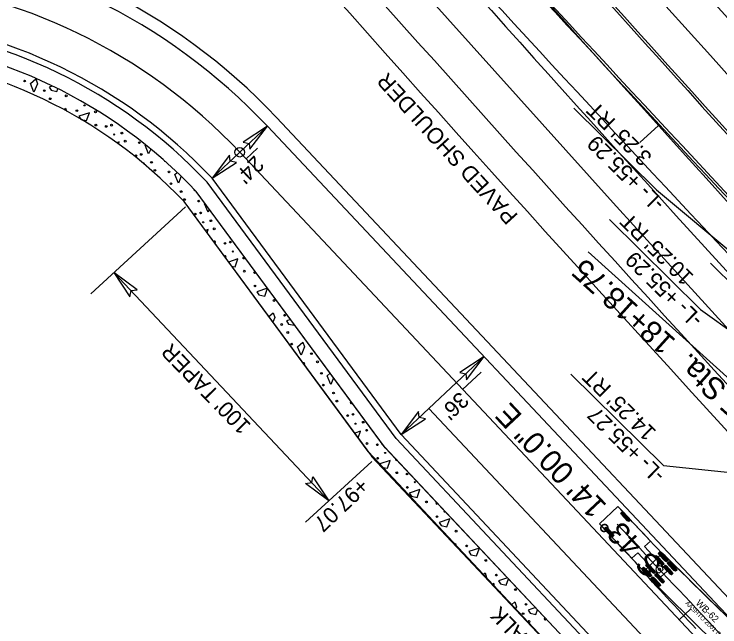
# Model space of a CAD drawing. Extents: x 1262642 to 1268358, y 767825 to 773481.
# Drawn here: x 1266385.4 to 1266608.5, y 772219.4 to 772413.2 of the extents above; entities that cross this region are included whole.
import ezdxf

# ---------------------------------------------------------------- set-up
doc = ezdxf.new("R2010")
doc.units = 0
for name, color, linetype in [('Default', 7, 'Continuous'), ('Prop Conc 1ft 6in Curb and Gutter', 7, 'Continuous'), ('Prop Conc 2ft 6in Curb and Gutter', 7, 'Continuous'), ('Prop Conc 4in Sidewalk', 7, 'Continuous'), ('Prop Dimension', 7, 'Continuous'), ('Prop Dimension Text', 7, 'Continuous'), ('Prop EOT', 7, 'Continuous'), ('Prop Horizontal Alignment', 7, 'Continuous'), ('Prop Horizontal Alignment Direction Label', 7, 'Continuous'), ('Prop Horizontal Alignment Station Label', 7, 'Continuous'), ('Prop Horizontal Alignment Tick Large', 7, 'Continuous'), ('Prop Horizontal Alignment Tick Small', 7, 'Continuous'), ('Prop Lane Lines', 7, 'Continuous'), ('Prop Paved Shoulder', 7, 'Continuous'), ('Prop Shade Light', 7, 'Continuous'), ('Prop Terminator CELL', 7, 'Continuous'), ('Scratch_Level_3', 7, 'Continuous')]:
    doc.layers.add(name, color=color, linetype=linetype)

msp = doc.modelspace()

# ---------------------------------------------------------------- linework, layer by layer
at = {"layer": 'Default'}
for p, q in [((1266447.96, 772361.32), (1266465.44, 772377.76)), ((1266507.71, 772280.24), (1266533.94, 772304.9))]:
    msp.add_line(p, q, dxfattribs=at)
at = {"layer": 'Prop Conc 1ft 6in Curb and Gutter'}
for centre, radius, start, end in [((1275047.31, 780021.23), 11385.75, 220.946412, 223.103661), ((1274932.68, 780143.08), 11396.75, 221.786199, 223.669794)]:
    msp.add_arc(centre, radius, start, end, dxfattribs=at)
at = {"layer": 'Prop Conc 2ft 6in Curb and Gutter'}
for p, q in [((1266390.56, 772391.24), (1266392.25, 772392.74)), ((1266391.64, 772388.56), (1266390.56, 772391.24)), ((1266392.77, 772391.21), (1266391.64, 772388.56)), ((1266392.25, 772392.74), (1266392.77, 772391.21)), ((1266397.45, 772390.49), (1266396.47, 772390.16)), ((1266396.47, 772390.16), (1266397.11, 772389.17)), ((1266397.11, 772389.17), (1266398.92, 772388.8)), ((1266398.92, 772388.8), (1266399.22, 772389.61)), ((1266401.08, 772383.01), (1266401.63, 772383.49)), ((1266401.63, 772383.49), (1266401.95, 772382.56)), ((1266409.22, 772382.05), (1266405.85, 772380.91)), ((1266405.85, 772380.91), (1266406.49, 772379.94)), ((1266406.53, 772379.92), (1266408.3, 772379.55)), ((1266408.3, 772379.55), (1266409.22, 772382.05)), ((1266418.61, 772372.8), (1266417.8, 772372.53)), ((1266418.36, 772372.13), (1266418.61, 772372.8)), ((1266426.83, 772371.75), (1266426.96, 772371.86)), ((1266427.91, 772369.07), (1266426.83, 772371.75)), ((1266428.55, 772370.56), (1266427.91, 772369.07)), ((1266436.22, 772362.5), (1266436.94, 772363.14)), ((1266437.3, 772359.82), (1266436.22, 772362.5)), ((1266438.21, 772361.96), (1266437.3, 772359.82)), ((1266506.17, 772278.96), (1266446.42, 772360.04)), ((1266502.71, 772276.07), (1266442.96, 772357.15)), ((1266497.36, 772274.9), (1266439.11, 772353.93)), ((1266445.6, 772353.26), (1266445.74, 772353.38)), ((1266446.68, 772350.58), (1266445.6, 772353.26)), ((1266447.09, 772351.54), (1266446.68, 772350.58)), ((1266446.76, 772345.07), (1266445.87, 772344.77)), ((1266446.39, 772344.06), (1266446.76, 772345.07)), ((1266456.14, 772335.82), (1266453.2, 772334.83)), ((1266455.22, 772333.32), (1266456.14, 772335.82)), ((1266454.14, 772333.55), (1266455.22, 772333.32)), ((1266465.5, 772326.57), (1266462.16, 772325.44)), ((1266464.61, 772324.08), (1266465.51, 772326.54)), ((1266462.16, 772325.44), (1266462.8, 772324.45)), ((1266462.8, 772324.45), (1266464.61, 772324.08)), ((1266465.93, 772317.55), (1266467.31, 772318.77)), ((1266467.31, 772318.77), (1266467.84, 772317.24)), ((1266467.84, 772317.24), (1266467.22, 772315.8)), ((1266472.82, 772316.62), (1266471.54, 772316.19)), ((1266471.54, 772316.19), (1266472.18, 772315.21)), ((1266472.18, 772315.21), (1266473.99, 772314.83)), ((1266473.99, 772314.83), (1266474.04, 772314.97)), ((1266475.01, 772308.03), (1266476.7, 772309.53)), ((1266476.7, 772309.53), (1266477.22, 772307.99)), ((1266476.09, 772305.35), (1266475.01, 772308.03)), ((1266477.22, 772307.99), (1266476.09, 772305.35)), ((1266484.4, 772298.79), (1266485.35, 772299.63)), ((1266485.48, 772296.11), (1266484.4, 772298.79)), ((1266486.38, 772298.23), (1266485.48, 772296.11)), ((1266494.93, 772281.35), (1266493.07, 772280.72)), ((1266494.16, 772279.24), (1266494.93, 772281.35)), ((1266506.17, 772278.96), (1266647.88, 772128.24)), ((1266502.71, 772276.07), (1266644.44, 772125.33)), ((1266497.36, 772274.9), (1266640.83, 772121.86)), ((1266504.32, 772272.1), (1266501.03, 772270.99)), ((1266503.4, 772269.6), (1266504.32, 772272.1)), ((1266502.07, 772269.88), (1266503.4, 772269.6)), ((1266513.7, 772262.86), (1266510.33, 772261.72)), ((1266510.33, 772261.72), (1266510.98, 772260.73)), ((1266512.78, 772260.36), (1266513.7, 772262.86)), ((1266510.98, 772260.73), (1266512.78, 772260.36)), ((1266523.09, 772253.61), (1266519.72, 772252.47)), ((1266522.17, 772251.11), (1266523.09, 772253.61)), ((1266519.72, 772252.47), (1266520.36, 772251.49)), ((1266520.36, 772251.49), (1266522.17, 772251.11)), ((1266524.74, 772245.69), (1266524.88, 772245.81)), ((1266524.88, 772245.81), (1266525.01, 772245.4)), ((1266532.47, 772244.36), (1266529.1, 772243.23)), ((1266531.55, 772241.87), (1266532.47, 772244.36)), ((1266529.1, 772243.23), (1266529.74, 772242.24)), ((1266529.74, 772242.24), (1266531.55, 772241.87)), ((1266533.74, 772236.1), (1266534.26, 772236.56)), ((1266534.26, 772236.56), (1266534.78, 772235.03)), ((1266534.78, 772235.03), (1266534.77, 772235)), ((1266541.37, 772234.96), (1266538.48, 772233.98)), ((1266538.48, 772233.98), (1266539.13, 772233)), ((1266539.13, 772233), (1266540.93, 772232.62)), ((1266540.93, 772232.62), (1266541.67, 772234.63)), ((1266542.73, 772226.51), (1266543.64, 772227.32)), ((1266543.64, 772227.32), (1266544.17, 772225.78)), ((1266544.17, 772225.78), (1266543.93, 772225.23)), ((1266550.23, 772225.53), (1266547.87, 772224.73)), ((1266547.87, 772224.73), (1266548.51, 772223.75)), ((1266548.51, 772223.75), (1266550.32, 772223.37)), ((1266550.32, 772223.37), (1266550.86, 772224.86))]:
    msp.add_line(p, q, dxfattribs=at)
for centre, radius in [((1266388.7, 772392.07), 0.268), ((1266394.91, 772389.04), 0.268), ((1266396.81, 772386.49), 0.292), ((1266401.86, 772387.39), 0.289), ((1266407.61, 772384.38), 0.18), ((1266405.22, 772382.72), 0.268), ((1266411.12, 772382.32), 0.285), ((1266411.24, 772378.14), 0.289), ((1266414.51, 772377.72), 0.268), ((1266416.19, 772378.11), 0.268), ((1266419.43, 772375.61), 0.268), ((1266416.99, 772375.14), 0.18), ((1266420.51, 772373.07), 0.285), ((1266424.97, 772372.58), 0.268), ((1266423.9, 772368.47), 0.268), ((1266425.57, 772368.86), 0.268), ((1266428.81, 772366.37), 0.268), ((1266429.89, 772363.83), 0.285), ((1266434.36, 772363.33), 0.268), ((1266434.96, 772359.61), 0.268), ((1266438.19, 772357.12), 0.268), ((1266439.27, 772354.58), 0.285), ((1266443.74, 772354.09), 0.268), ((1266442.66, 772349.98), 0.268), ((1266444.34, 772350.37), 0.268), ((1266445.14, 772347.4), 0.18), ((1266447.58, 772347.87), 0.268), ((1266448.66, 772345.34), 0.285), ((1266452.05, 772340.73), 0.268), ((1266453.72, 772341.12), 0.268), ((1266454.53, 772338.16), 0.18), ((1266458.04, 772336.09), 0.285), ((1266458.16, 772331.91), 0.289), ((1266461.43, 772331.49), 0.268), ((1266461.52, 772327.25), 0.268), ((1266467.54, 772322.67), 0.289), ((1266470.9, 772318), 0.268), ((1266469.98, 772315.07), 0.268), ((1266471.88, 772312.52), 0.292), ((1266473.15, 772308.86), 0.268), ((1266479.37, 772305.82), 0.268), ((1266481.27, 772303.28), 0.292), ((1266482.53, 772299.62), 0.268), ((1266483.13, 772295.9), 0.268), ((1266486.37, 772293.4), 0.268), ((1266487.45, 772290.86), 0.285), ((1266490.84, 772286.26), 0.268), ((1266492.52, 772286.65), 0.268), ((1266495.76, 772284.16), 0.268), ((1266493.32, 772283.68), 0.18), ((1266496.84, 772281.62), 0.285), ((1266496.95, 772277.44), 0.289), ((1266500.22, 772277.02), 0.268), ((1266500.31, 772272.78), 0.268), ((1266502.7, 772274.44), 0.18), ((1266506.34, 772268.19), 0.289), ((1266509.61, 772267.77), 0.268), ((1266512.09, 772265.19), 0.18), ((1266509.7, 772263.53), 0.268), ((1266515.72, 772258.95), 0.289), ((1266519.08, 772254.29), 0.268), ((1266525.11, 772249.7), 0.289), ((1266528.46, 772245.04), 0.268), ((1266534.49, 772240.46), 0.289), ((1266537.85, 772235.79), 0.268), ((1266543.87, 772231.21), 0.289), ((1266547.23, 772226.55), 0.268), ((1266546.31, 772223.61), 0.268)]:
    msp.add_circle(centre, radius, dxfattribs=at)
for centre, radius, start, end in [((1266329.2, 772249.67), 161, 43.2758, 125.8167), ((1266329.2, 772249.67), 156.5, 43.3742, 125.8167), ((1266329.2, 772249.67), 151.5, 43.4886, 125.8167), ((1266433.09, 772366.99), 0.292, 186.536, 271.698), ((1266426.38, 772365.89), 0.18, 350.1757, 149.8364), ((1266426.38, 772365.89), 0.18, 309.7917, 350.1757), ((1266442.47, 772357.75), 0.292, 150.1108, 299.1636), ((1266448.78, 772341.16), 0.289, 263.1236, 169.6575), ((1266452.14, 772336.5), 0.268, 275.6877, 157.0934), ((1266463.91, 772328.91), 0.18, 165.6129, 267.1682), ((1266462.5, 772321.77), 0.292, 8.8332, 63.9479), ((1266476.99, 772302.65), 0.268, 293.3734, 139.4078), ((1266483.94, 772292.93), 0.18, 344.51, 88.2711), ((1266491.92, 772290.37), 0.268, 76.2831, 356.498), ((1266501.9, 772277.4), 0.268, 157.7095, 275.0716), ((1266506.22, 772272.37), 0.285, 137.8046, 308.6621), ((1266518.99, 772258.52), 0.268, 97.1815, 349.2851), ((1266521.47, 772255.95), 0.18, 92.5925, 353.8742), ((1266536.93, 772232.86), 0.268, 288.311, 157.9917), ((1266538.83, 772230.31), 0.292, 9.7383, 76.5643), ((1266553.26, 772221.96), 0.289, 78.3196, 8.1471), ((1266548.21, 772221.07), 0.292, 240.1864, 206.1162)]:
    msp.add_arc(centre, radius, start, end, dxfattribs=at)
at = {"layer": 'Prop Conc 4in Sidewalk'}
for p, q in [((1266502.48, 772276.39), (1266442.96, 772357.15)), ((1266498.45, 772273.42), (1266439.11, 772353.93)), ((1266502.44, 772276.36), (1266644.6, 772125.15)), ((1266498.39, 772273.36), (1266640.96, 772121.73))]:
    msp.add_line(p, q, dxfattribs=at)
for radius, start in [(156.5, 43.3742), (151.5, 43.4886)]:
    msp.add_arc((1266329.2, 772249.67), radius, start, 125.8167, dxfattribs=at)
at = {"layer": 'Prop Dimension Text'}
for p, q in [((1266562.29, 772383.47), (1266588.48, 772357.65)), ((1266588.48, 772357.65), (1266689.12, 772273.54)), ((1266439.59, 772352.32), (1266409.59, 772324.77)), ((1266573.6, 772348.23), (1266602.44, 772319.81)), ((1266605.51, 772334.48), (1266637.67, 772302.8)), ((1266484.88, 772259.28), (1266416.95, 772331.53)), ((1266602.44, 772319.81), (1266679.28, 772264.3)), ((1266561.38, 772299.36), (1266590.66, 772270.5)), ((1266498.46, 772271.75), (1266477.52, 772252.52)), ((1266590.66, 772270.5), (1266676.36, 772261.56))]:
    msp.add_line(p, q, dxfattribs=at)
for points in [[(1266424.25, 772326.04), (1266416.95, 772331.53), (1266421.99, 772323.84), (1266422.37, 772325.78)], [(1266479.85, 772266.9), (1266484.88, 772259.28), (1266477.52, 772264.78), (1266479.47, 772265.04)]]:
    msp.add_lwpolyline(points, close=True, dxfattribs=at)
at = {"layer": 'Prop EOT'}
for p, q in [((1266465.44, 772377.76), (1266608.52, 772225.58)), ((1266507.71, 772280.24), (1266447.96, 772361.32)), ((1266507.71, 772280.24), (1266649.33, 772129.6))]:
    msp.add_line(p, q, dxfattribs=at)
for centre, radius, start, end in [((1275047.31, 780021.23), 11361, 216.766365, 222.716029), ((1275047.31, 780021.23), 11439, 220.505091, 222.993587), ((1275047.31, 780021.23), 11385, 220.946412, 222.993587), ((1274932.68, 780143.08), 11397.5, 221.785983, 223.669794), ((1266329.2, 772249.67), 187, 43.2333, 84.9916), ((1266329.2, 772249.67), 163, 43.2333, 125.8167), ((1266840.27, 772443.46), 318.09, 223.2333, 243.6532)]:
    msp.add_arc(centre, radius, start, end, dxfattribs=at)
at = {"layer": 'Prop Horizontal Alignment'}
msp.add_line((1266456.7, 772369.54), (1266660.64, 772152.62), dxfattribs=at)
for centre, radius, start, end in [((1275047.31, 780021.23), 11400, 216.766365, 222.993587), ((1266329.2, 772249.67), 175, 43.2333, 125.8167)]:
    msp.add_arc(centre, radius, start, end, dxfattribs=at)
at = {"layer": 'Prop Horizontal Alignment Station Label'}
msp.add_line((1266769.82, 772154.72), (1266566.88, 772338.06), dxfattribs=at)
msp.add_circle((1266456.7, 772369.54), 1.5, dxfattribs=at)
at = {"layer": 'Prop Horizontal Alignment Tick Large'}
for p, q in [((1266589.1, 772378.01), (1266583.16, 772372.65)), ((1266527.19, 772294.56), (1266533.02, 772300.04))]:
    msp.add_line(p, q, dxfattribs=at)
at = {"layer": 'Prop Horizontal Alignment Tick Small'}
for p, q in [((1266458.7, 772367.42), (1266462.34, 772370.84)), ((1266595.69, 772221.7), (1266599.33, 772225.13))]:
    msp.add_line(p, q, dxfattribs=at)
at = {"layer": 'Prop Lane Lines'}
msp.add_line((1266516.45, 772288.46), (1266651.9, 772144.4), dxfattribs=at)
for centre, radius, start, end in [((1275047.31, 780021.23), 11373, 216.364944, 223.132748), ((1275047.31, 780021.23), 11427, 216.367499, 223.547684), ((1275047.31, 780021.23), 11415, 220.946412, 223.104121), ((1274932.68, 780143.08), 11409.5, 221.786199, 223.669794)]:
    msp.add_arc(centre, radius, start, end, dxfattribs=at)
at = {"layer": 'Prop Paved Shoulder'}
msp.add_line((1266468.36, 772380.5), (1266611.43, 772228.32), dxfattribs=at)
for centre, radius, start, end in [((1275047.31, 780021.23), 11351, 216.766365, 222.716029), ((1275047.31, 780021.23), 11449, 220.505091, 223.202447), ((1266329.2, 772249.67), 191, 43.2333, 84.9916)]:
    msp.add_arc(centre, radius, start, end, dxfattribs=at)
at = {"layer": 'Prop Shade Light'}
for p, q in [((1266611.43, 772228.32), (1266468.36, 772380.5)), ((1266465.44, 772377.76), (1266608.52, 772225.58))]:
    msp.add_line(p, q, dxfattribs=at)
for centre, radius, start, end in [((1275047.31, 780021.23), 11351, 216.765763, 222.716029), ((1275047.31, 780021.23), 11361, 216.765886, 222.716029), ((1275047.31, 780021.23), 11439, 220.505091, 222.993587), ((1275047.31, 780021.23), 11449, 220.505091, 223.202447), ((1266329.2, 772249.67), 191, 43.2333, 84.9916), ((1266329.2, 772249.67), 187, 43.2333, 84.9916)]:
    msp.add_arc(centre, radius, start, end, dxfattribs=at)
at = {"layer": 'Prop Terminator CELL'}
for points in [[(1266459.95, 772370.47), (1266465.44, 772377.76), (1266457.75, 772372.73), (1266459.69, 772372.35)], [(1266453.45, 772368.61), (1266447.96, 772361.32), (1266455.65, 772366.35), (1266453.71, 772366.73)], [(1266528.44, 772297.61), (1266533.94, 772304.9), (1266526.25, 772299.87), (1266528.18, 772299.49)], [(1266513.21, 772287.54), (1266507.71, 772280.24), (1266515.4, 772285.28), (1266513.47, 772285.66)]]:
    msp.add_lwpolyline(points, close=True, dxfattribs=at)
at = {"layer": 'Scratch_Level_3'}
for p, q in [((1266576.27, 772257.53), (1266570.43, 772252.06)), ((1266586.53, 772246.58), (1266576.27, 772257.53)), ((1266577.26, 772255.48), (1266579.75, 772252.8)), ((1266577.42, 772255.64), (1266579.92, 772252.95)), ((1266577.59, 772255.79), (1266580.09, 772253.11)), ((1266570.43, 772252.06), (1266580.69, 772241.11)), ((1266570.43, 772252.06), (1266570.43, 772252.06)), ((1266572.08, 772250.64), (1266574.58, 772247.96)), ((1266572.25, 772250.8), (1266574.75, 772248.11)), ((1266572.42, 772250.95), (1266574.92, 772248.27)), ((1266584.65, 772244.83), (1266586.53, 772246.58)), ((1266591.89, 772237.1), (1266584.65, 772244.83)), ((1266580.69, 772241.11), (1266582.56, 772242.87)), ((1266582.56, 772242.87), (1266589.79, 772235.14)), ((1266590.26, 772242.78), (1266584.3, 772236.71)), ((1266587.95, 772241.64), (1266590.46, 772238.96)), ((1266588.12, 772241.79), (1266590.63, 772239.12)), ((1266588.29, 772241.95), (1266590.79, 772239.27)), ((1266589.16, 772242.76), (1266591.66, 772240.09)), ((1266589.32, 772242.92), (1266591.83, 772240.24)), ((1266589.49, 772243.08), (1266592, 772240.4)), ((1266624.48, 772209.12), (1266590.26, 772242.78)), ((1266585.52, 772239.36), (1266588.03, 772236.69)), ((1266592, 772239.72), (1266594.51, 772237.05)), ((1266592.17, 772239.88), (1266594.68, 772237.2)), ((1266592.34, 772240.04), (1266594.85, 772237.36)), ((1266583.99, 772237.92), (1266586.49, 772235.25)), ((1266584.15, 772238.08), (1266586.66, 772235.4)), ((1266584.32, 772238.24), (1266586.83, 772235.56)), ((1266585.19, 772239.05), (1266587.7, 772236.37)), ((1266585.36, 772239.21), (1266587.86, 772236.53)), ((1266589.38, 772236.5), (1266590.56, 772237.6)), ((1266589.79, 772235.14), (1266591.89, 772237.1)), ((1266590.8, 772238.6), (1266593.31, 772235.92)), ((1266590.97, 772238.75), (1266593.47, 772236.08)), ((1266591.13, 772238.91), (1266593.64, 772236.23)), ((1266584.3, 772236.71), (1266618.52, 772203.06)), ((1266584.3, 772236.71), (1266584.3, 772236.71)), ((1266586.83, 772234.88), (1266589.34, 772232.2)), ((1266587, 772235.04), (1266589.51, 772232.36)), ((1266587.17, 772235.19), (1266589.67, 772232.52)), ((1266588.04, 772236.01), (1266590.54, 772233.33)), ((1266588.21, 772236.17), (1266590.71, 772233.49)), ((1266588.37, 772236.32), (1266590.88, 772233.65))]:
    msp.add_line(p, q, dxfattribs=at)
for points in [[(1266608.93, 772224.41), (1266607.75, 772225.58), (1266606.56, 772226.74), (1266605.38, 772227.9), (1266604.2, 772229.07), (1266603.01, 772230.23), (1266601.83, 772231.39), (1266600.65, 772232.56), (1266599.46, 772233.72), (1266598.28, 772234.89), (1266597.1, 772236.05), (1266595.91, 772237.21), (1266594.73, 772238.38), (1266593.54, 772239.54), (1266592.36, 772240.71), (1266591.17, 772241.87), (1266589.91, 772242.96), (1266588.77, 772244.17), (1266587.64, 772245.39), (1266586.5, 772246.6), (1266585.37, 772247.82), (1266584.23, 772249.03), (1266583.09, 772250.25), (1266581.96, 772251.46), (1266580.82, 772252.67), (1266579.68, 772253.89), (1266578.55, 772255.1), (1266577.41, 772256.31), (1266576.27, 772257.53)], [(1266600.88, 772218.95), (1266599.75, 772220.17), (1266598.61, 772221.39), (1266597.47, 772222.61), (1266596.33, 772223.82), (1266595.2, 772225.04), (1266594.06, 772226.26), (1266592.92, 772227.48), (1266591.79, 772228.7), (1266590.65, 772229.91), (1266589.52, 772231.13), (1266588.38, 772232.35), (1266587.24, 772233.57), (1266586.11, 772234.79), (1266584.97, 772236.01), (1266584.06, 772237.45), (1266582.92, 772238.67), (1266581.79, 772239.88), (1266580.65, 772241.1), (1266579.51, 772242.32), (1266578.38, 772243.53), (1266577.24, 772244.75), (1266576.11, 772245.97), (1266574.97, 772247.19), (1266573.84, 772248.4), (1266572.7, 772249.62), (1266571.57, 772250.84), (1266570.43, 772252.06)]]:
    msp.add_lwpolyline(points, dxfattribs=at)
for points in [[(1266577.21, 772255.44), (1266577.63, 772255.83), (1266578.11, 772255.57), (1266579.91, 772253.64), (1266580.13, 772253.15), (1266579.71, 772252.76), (1266579.24, 772253.02), (1266577.44, 772254.95)], [(1266572.04, 772250.6), (1266572.46, 772250.99), (1266572.94, 772250.73), (1266574.74, 772248.8), (1266574.96, 772248.31), (1266574.54, 772247.92), (1266574.06, 772248.18), (1266572.27, 772250.11)], [(1266587.91, 772241.6), (1266588.33, 772241.99), (1266588.8, 772241.73), (1266590.61, 772239.8), (1266590.83, 772239.31), (1266590.42, 772238.92), (1266589.94, 772239.18), (1266588.14, 772241.11)], [(1266589.11, 772242.73), (1266589.53, 772243.12), (1266590.01, 772242.86), (1266591.81, 772240.93), (1266592.04, 772240.44), (1266591.62, 772240.05), (1266591.14, 772240.31), (1266589.34, 772242.23)], [(1266585.15, 772239.01), (1266585.57, 772239.4), (1266586.04, 772239.15), (1266587.85, 772237.22), (1266588.07, 772236.73), (1266587.66, 772236.34), (1266587.18, 772236.59), (1266585.37, 772238.52)], [(1266591.96, 772239.68), (1266592.38, 772240.08), (1266592.86, 772239.82), (1266594.66, 772237.89), (1266594.89, 772237.4), (1266594.47, 772237.01), (1266593.99, 772237.26), (1266592.19, 772239.19)], [(1266583.94, 772237.88), (1266584.36, 772238.27), (1266584.84, 772238.02), (1266586.64, 772236.09), (1266586.87, 772235.6), (1266586.45, 772235.21), (1266585.97, 772235.46), (1266584.17, 772237.39)], [(1266590.76, 772238.56), (1266591.18, 772238.95), (1266591.65, 772238.69), (1266593.46, 772236.76), (1266593.68, 772236.27), (1266593.26, 772235.88), (1266592.79, 772236.14), (1266590.98, 772238.06)], [(1266586.79, 772234.84), (1266587.21, 772235.23), (1266587.69, 772234.98), (1266589.49, 772233.05), (1266589.72, 772232.56), (1266589.3, 772232.17), (1266588.82, 772232.42), (1266587.02, 772234.35)], [(1266588, 772235.97), (1266588.41, 772236.36), (1266588.89, 772236.1), (1266590.7, 772234.18), (1266590.92, 772233.68), (1266590.5, 772233.29), (1266590.03, 772233.55), (1266588.22, 772235.48)]]:
    msp.add_lwpolyline(points, close=True, dxfattribs=at)
msp.add_circle((1266589.42, 772237.64), 0.34, dxfattribs=at)
for centre, radius, start, end in [((1271970.4, 777276.39), 7371.86, 222.967251, 223.613894), ((1266589.42, 772237.64), 1.14, 358.1202, 268.1202)]:
    msp.add_arc(centre, radius, start, end, dxfattribs=at)

# ---------------------------------------------------------------- texts
at = {"layer": 'Prop Dimension'}
for s, rotation, p in [('PAVED SHOULDER', 132.3841, (1266544.95, 772349.58)), ("100' TAPER", 134.2575, (1266460.56, 772283.29))]:
    msp.add_text(s, height=5, rotation=rotation, dxfattribs=at).set_placement(p)
at = {"layer": 'Prop Dimension Text'}
for s, rotation, p in [("3.25' RT", 135.4239, (1266587.38, 772368.3)), ('-L- +55.29', 135.4239, (1266591.43, 772353.79)), ("24'", 223.4955, (1266461.45, 772368.79)), ("10.25' RT", 135.4239, (1266600.57, 772330.49)), ('-L- +55.29', 135.4239, (1266603.49, 772317.08)), ("14.25' RT", 135.4239, (1266588.67, 772281.3)), ("36'", 223.4955, (1266526.22, 772294.12)), ('-L- +55.27', 135.4239, (1266591.54, 772267.95)), ('+97.07', 223.3665, (1266494.67, 772266.9)), ("5' SIDEWALK", 133.4955, (1266567.55, 772196.23))]:
    msp.add_text(s, height=5, rotation=rotation, dxfattribs=at).set_placement(p)
at = {"layer": 'Prop Horizontal Alignment Direction Label'}
msp.add_text('S 43%%d 14\' 00.0" E', height=7, rotation=133.2333, dxfattribs=at).set_placement((1266590.6, 772239.21))
at = {"layer": 'Prop Horizontal Alignment Station Label'}
msp.add_text('PT Sta.  18+18.75', height=7, rotation=137.9038, dxfattribs=at).set_placement((1266621.93, 772285.63))
at = {"layer": 'Scratch_Level_3'}
for s, height, p in [('WB-62', 2.125, (1266600.72, 772226.76)), ('AASHTO 2001 (US)', 1.4167, (1266597.43, 772226.77)), ('(c) 2016 Transoft Solutions, Inc. All rights reserved.', 0.085, (1266603.12, 772224.1))]:
    msp.add_text(s, height=height, rotation=315.4849, dxfattribs=at).set_placement(p)

doc.saveas('drawing.dxf')
